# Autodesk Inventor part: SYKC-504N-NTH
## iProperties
Company: Engineering Services Northland (1988) Ltd
Author: Malcolm
Shininess: 60.0
PropertySet Name: _Private Model Information
Created: 2001-06
Part Number: SYKC-504N-NTH
Material: Stainless Steel, Austenitic
Description: Plummer Block S/S Bearing
Document SubType Name: Modeling
Designer: Malcolm
Control State: 0
Master: False
Checked Out: False
PropertySet Name: Design Tracking Control
Density: 0.0
Volumn: 0.0
Area: 0.0
PropertySet Name: Model Information
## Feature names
1. Extrusion7
2. Extrusion8
3. Extrusion9
4. Extrusion10
5. Extrusion11
6. Extrusion12
7. Fillet9
8. Fillet8
9. Fillet10
10. Revolution1
11. Hole1
12. Hole2
